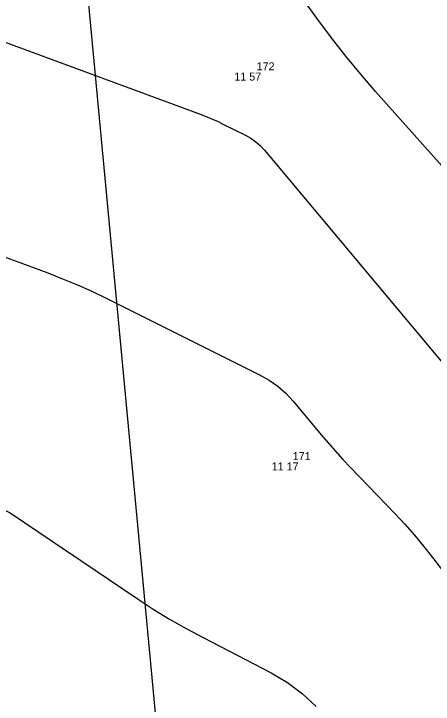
# Model space of a CAD drawing. Extents: x -711234 to -710007, y -1026313 to -1025448.
# Drawn here: x -710893.7 to -710879.04, y -1025865.86 to -1025841.72 of the extents above; entities that cross this region are included whole.
import ezdxf

# ---------------------------------------------------------------- set-up
doc = ezdxf.new("R2010")
doc.units = 0
for name, color, linetype in [('Ex_Major Contours', 7, 'Continuous'), ('Ex_Minor Contours', 7, 'Continuous'), ('Z_body', 7, 'Continuous'), ('Z_body_cisla', 7, 'Continuous'), ('Z_body_vysky_redukovane', 7, 'Continuous'), ('Z_katastr_hranice', 7, 'Continuous')]:
    doc.layers.add(name, color=color, linetype=linetype)

# ---------------------------------------------------------------- blocks, each defined once
blk = doc.blocks.new('POINT_DISPLAY')
blk.add_line((0, 0), (0, 0))

msp = doc.modelspace()

# ---------------------------------------------------------------- linework, layer by layer
at = {"layer": 'Ex_Major Contours'}
msp.add_lwpolyline([(-710895.03, -1025866.046), (-710894.978, -1025864.801), (-710894.967, -1025864.49), (-710894.96, -1025864.178), (-710894.958, -1025863.867), (-710894.961, -1025863.556), (-710895.017, -1025859.815), (-710894.951, -1025859.23), (-710894.731, -1025858.928), (-710894.358, -1025858.909), (-710893.832, -1025859.174), (-710889.386, -1025862.171), (-710888.826, -1025862.538), (-710888.255, -1025862.887), (-710887.675, -1025863.22), (-710887.084, -1025863.536), (-710884.703, -1025864.767), (-710884.131, -1025865.103), (-710883.607, -1025865.495), (-710883.129, -1025865.943)], dxfattribs=at)
at = {"layer": 'Ex_Minor Contours'}
for points in [[(-710872.836, -1025853.653), (-710881.053, -1025844.438), (-710881.583, -1025843.828), (-710882.096, -1025843.206), (-710882.594, -1025842.57), (-710883.075, -1025841.92), (-710885.007, -1025839.241)], [(-710894.809, -1025842.423), (-710887.154, -1025845.248), (-710886.954, -1025845.325), (-710886.755, -1025845.407), (-710886.559, -1025845.495), (-710886.365, -1025845.589), (-710885.595, -1025845.973), (-710885.409, -1025846.078), (-710885.237, -1025846.2), (-710885.078, -1025846.339), (-710884.933, -1025846.495), (-710878.467, -1025854.22)], [(-710895.048, -1025849.849), (-710892.512, -1025850.785), (-710891.993, -1025850.985), (-710891.479, -1025851.199), (-710890.971, -1025851.426), (-710890.47, -1025851.668), (-710885.106, -1025854.343), (-710884.776, -1025854.529), (-710884.47, -1025854.745), (-710884.189, -1025854.992), (-710883.931, -1025855.27), (-710882.95, -1025856.443), (-710882.702, -1025856.734), (-710882.449, -1025857.021), (-710882.192, -1025857.303), (-710881.929, -1025857.581), (-710880.37, -1025859.205), (-710880.027, -1025859.572), (-710879.695, -1025859.948), (-710879.373, -1025860.334), (-710879.062, -1025860.728), (-710874.8, -1025866.29)]]:
    msp.add_lwpolyline(points, dxfattribs=at)
at = {"layer": 'Z_katastr_hranice'}
msp.add_lwpolyline([(-710900.43, -1025767.22), (-710899.08, -1025775.57), (-710892.41, -1025827.39), (-710888.58, -1025868.03)], dxfattribs=at)

# ---------------------------------------------------------------- block references
at = {"layer": 'Z_body'}
for p in [(-710885.43, -1025843.78), (-710884.17, -1025857.41)]:
    msp.add_blockref('POINT_DISPLAY', p, dxfattribs=at)

# ---------------------------------------------------------------- texts
at = {"layer": 'Z_body_cisla'}
for s, p in [('172', (-710885.21, -1025843.7)), ('171', (-710883.95, -1025857.33))]:
    msp.add_text(s, height=0.28, dxfattribs=at).set_placement(p)
at = {"layer": 'Z_body_vysky_redukovane'}
for s, p in [('11 57', (-710885.99, -1025844.06)), ('11 17', (-710884.683, -1025857.69))]:
    msp.add_text(s, height=0.28, dxfattribs=at).set_placement(p)

doc.saveas('drawing.dxf')
